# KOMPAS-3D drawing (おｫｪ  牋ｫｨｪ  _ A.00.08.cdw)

Views: Спереди 1, Спереди, Проекционный вид 2, Проекционный вид 3, Проекционный вид 4, Проекционный вид 5, Проекционный вид 6, Изометрия XYZ 7, Изометрия XYZ
Referenced files in C:\Users\s.slezkin\Desktop\Раскатчик арок 2\: Вилка ролика _ A.00.08.m3d, Вилка ролика _ A.00.08.cdw
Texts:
  Вилка ролика
  http://vk.com/sergey_krd
  1. Трубу квадратную с листом S=3 сварить по
  ГОСТ 5264-80;
  2. Штангу изготовить из труб стальной квадратной
  40x40x2 ГОСТ 8639-82 и листа стального S=3
  ГОСТ 19904-90.
Dimensions and other numbers on the sheet: 10; 2 отв.; 7; 15; 42; 53; 3; 72; 20; 19; 2; 50; 9; 9,5; 25; 40; 5; 1:1; 1; 0,29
